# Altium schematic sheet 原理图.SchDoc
size A4
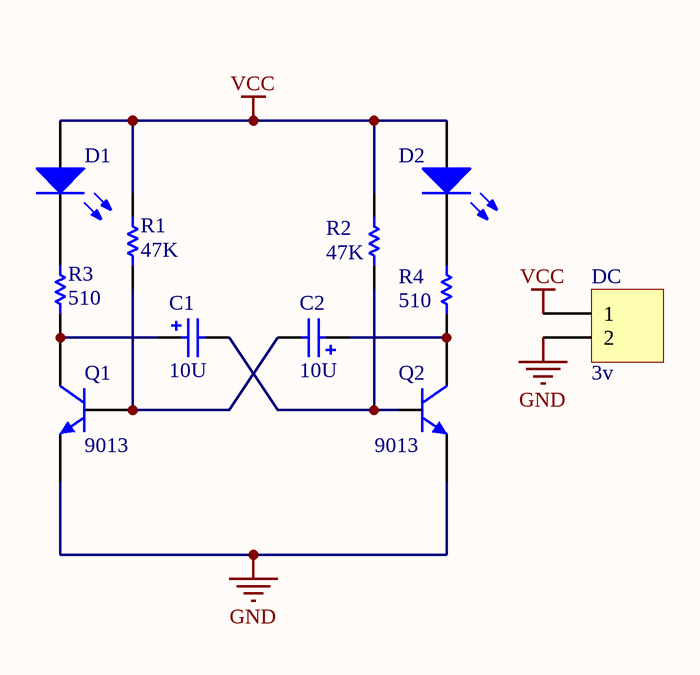
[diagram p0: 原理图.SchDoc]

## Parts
C1  10U  [CAPPR2-5x6.8]
C2  10U  [CAPPR2-5x6.8]
D1  LED0  [CAPPR2-5x6.8]  (value not drawn)
D2  LED0  [CAPPR2-5x6.8]  (value not drawn)
DC  3v  [HDR1X2]
Q1  9013  [BCY-W3/E4]
Q2  9013  [BCY-W3/E4]
R1  47K  [AXIAL-0.3]
R2  47K  [AXIAL-0.3]
R3  510  [AXIAL-0.3]
R4  510  [AXIAL-0.3]

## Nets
GND: DC.2 Q1.1(E) Q2.1(E)
VCC: D1.1(A) D2.1(A) DC.1 R1.2 R2.2
NetC1_1: C1.1 Q1.3(C) R3.1
NetC1_2: C1.2 Q2.2(B) R2.1
NetC2_1: C2.1 Q2.3(C) R4.1
NetC2_2: C2.2 Q1.2(B) R1.1
NetD1_2: D1.2(K) R3.2
NetD2_2: D2.2(K) R4.2

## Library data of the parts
C1 C2 = Cap Pol2: Polarized Capacitor (Axial); Value: 100pF
D1 D2 = LED0: Typical INFRARED GaAs LED
DC = Header 2: Header, 2-Pin
Q1 Q2 = 2N3904: NPN General Purpose Amplifier
R1-R4 = Res1: Resistor; Value: 1K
